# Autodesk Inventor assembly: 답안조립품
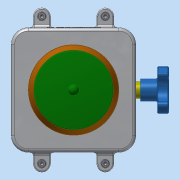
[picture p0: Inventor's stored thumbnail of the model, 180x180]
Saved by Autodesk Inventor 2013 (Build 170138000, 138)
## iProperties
Created: 2018-01
Part Number: 답안조립품
Document SubType Name: Assembly
Designer: dgall
Author: dgall
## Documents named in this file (9)
- C:\Users\dgall\Desktop\480107V1043\답안조립품.iam
- C:\Users\dgall\Desktop\480107V1043\답안본체.ipt
- C:\Users\dgall\Desktop\480107V1043\본체커버.ipt
- C:\Users\dgall\Desktop\480107V1043\볼트 M3x12.ipt
- C:\Users\dgall\Desktop\480107V1043\볼트 M4x12.ipt
- C:\Users\dgall\Desktop\480107V1043\용기.ipt
- C:\Users\dgall\Desktop\480107V1043\용기캡.ipt
- C:\Users\dgall\Desktop\480107V1043\핸들.ipt
- C:\Users\dgall\Desktop\480107V1043\핸들축.ipt
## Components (2 placed, 2 different names)
1. 핸들:1 — 각도:1
2. 핸들축:1 — 각도:1
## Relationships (1: Angle 1)
- 각도:1 [Angle]: 핸들:1 ↔ 핸들축:1
